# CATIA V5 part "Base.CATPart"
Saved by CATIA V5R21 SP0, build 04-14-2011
Part number: Part1
Bounding box of the stored display mesh (mm): x -50 to 50, y -25 to 25, z 0 to 50
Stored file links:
  D:\CATIA V5R21 E-RESOURCES\CATIA-V5R21\catia-v5r21-prt\c12-catia-v5r20-prt\c12-catia-v5-r20-figr-12-12\cat_v5r21_Base.CATPart
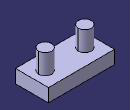
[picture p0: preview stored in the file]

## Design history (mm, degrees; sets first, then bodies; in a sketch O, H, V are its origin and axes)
Body1 (main body)
  Sketch1 on xy-plane, origin (0, 0, 0), H (1, 0, 0), V (0, 1, 0)
    line L1 (50, 25) -> (50, -25)
    line L2 (50, -25) -> (-50, -25)
    line L3 (-50, -25) -> (-50, 25)
    line L4 (-50, 25) -> (50, 25)
    circle A1 centre (-30, 0) radius 10
    point P5 (-30, 0)
    circle A2 centre (30, 0) radius 10
    length L2 = 100
    length L1 = 50
    radius A1 = 10
    distance P5 V = 30
    vertical: L1 V, L3 V
    horizontal: L2 H, L4 H
    equidistance: L1 L3 O, L2 L4 O
    coincidence: P5 H
    symmetry: A1 A2 V
  MultiPad1: profile Sketch1, domains (length 20; length 50; length 50)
